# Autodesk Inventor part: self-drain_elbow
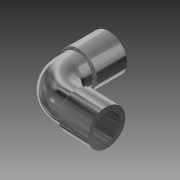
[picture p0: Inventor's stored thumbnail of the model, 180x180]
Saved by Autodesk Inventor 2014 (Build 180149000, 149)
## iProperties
Created: 2007-10
Part Number: self-drain_elbow
Document SubType Name: Modeling
Designer: hassen
Density: 1 g/cm^3
Categories: <MemberInstance><Categories><Category DisplayName="" InternalName="4347fa0f-2144-441d-94cd-e3e15c92b736" Mnemonic="TUBEANDPIPE"><CategoryParameter DisplayName="
Material: Generic
Appearance: Steel - Polished
Author: hassen
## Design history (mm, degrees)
sketch "Sketch1"
  geometry: L1 (0, 0)-(0, -38.1); L2 (24.128, -63.085)-(62.204, -64.414); A1 r 25 centre (25, -38.1) between (0, -38.1) and (24.128, -63.085)
  constraints: 4 end point, 2 point on circle, 2 tangent, 1 centre point, 1 vertical
  dimensions: "d0" = 38.1 distance of L1.start L1.end; "d1" = 38.1 distance of L2.start L2.end; "d2" = 25 radius of A1; "d25" = 88 deg angle of L1 L2
sketch "Sketch2"
  geometry: C1 r 15.24 at (0, 0); 1 further point
  constraints: 1 centre point, 1 coincident
  dimensions: "d3" = 30.48 diameter of C1
sweep "Sweep1" sketch "Sketch2" dims "d4" = 0
sketch "Sketch5"
  geometry: C1 r 15.24 at (0, 0) reference; C2 r 12.7 at (0, 0)
  constraints: 1 centre point, 1 coincident
  dimensions: "d12" = 25.4 diameter of C2
sweep "Sweep2" sketch "Sketch5" dims "d13" = 0
sketch "Sketch6"
  geometry: C1 r 15.24 at (0, 0) reference; C2 r 17.5 at (0, 0)
  constraints: 1 centre point, 1 coincident
  dimensions: "d14" = 35 diameter of C2
extrude "Extrusion3" join sketch "Sketch6" distance "d15" = 30; taper "d16" = 0 deg
sketch "Sketch7"
  geometry: C1 r 15.24 at (0, 0) reference; C2 r 17.5 at (0, 0); 1 further point
  constraints: 1 centre point, 1 coincident
  dimensions: "d17" = 35 diameter of C2 (= d14)
extrude "Extrusion4" join sketch "Sketch7" distance "d18" = 30 (= d15); taper "d19" = 0 deg
fillet "Fillet1" dims "d20" = 1
thread "Thread3" dims "d26" = 25.4, "d27" = 0
thread "Thread4" dims "d28" = 25.4, "d29" = 0
body "Solid1"
